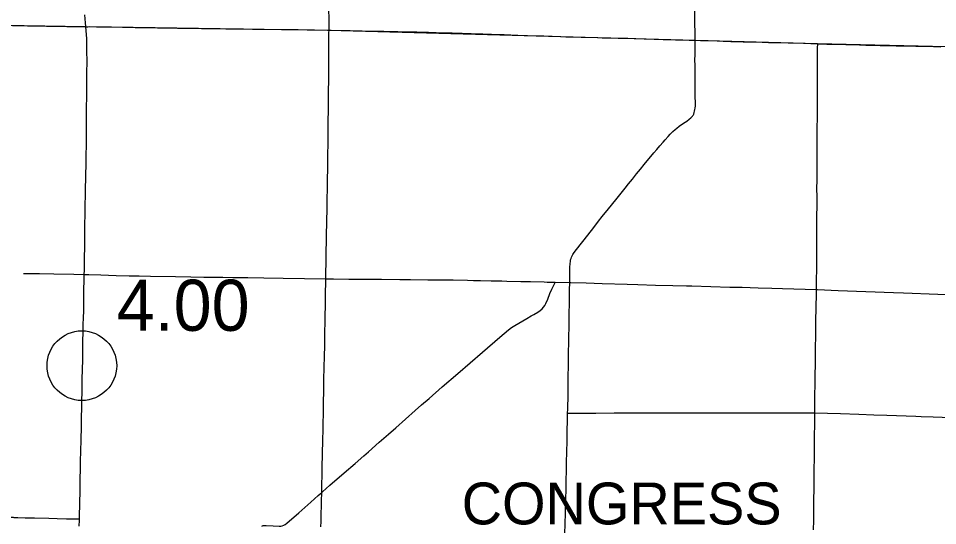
# Model space of a CAD drawing. Extents: x 1813937 to 1948437, y 826606 to 1022856.
# Drawn here: x 1893278 to 1913070, y 950713 to 961626 of the extents above; entities that cross this region are included whole.
import ezdxf

# ---------------------------------------------------------------- set-up
doc = ezdxf.new("R2010")
doc.units = 0
for name, color, linetype in [('Default', 7, 'Continuous'), ('GM_X_County_Road', 7, 'Continuous'), ('GM_X_State_Route', 7, 'Continuous'), ('GM_X_Township', 7, 'Continuous'), ('GM_X_Township_Road', 7, 'Continuous'), ('GM_X_Township_Text', 7, 'Continuous')]:
    doc.layers.add(name, color=color, linetype=linetype)

msp = doc.modelspace()

# ---------------------------------------------------------------- linework, layer by layer
at = {"layer": 'Default'}
msp.add_circle((1894644, 954154), 750, dxfattribs=at)
at = {"layer": 'GM_X_County_Road'}
for points in [[(1899966, 961373), (1899966, 961413), (1899967, 961609), (1899965, 961822)], [(1907848, 961156), (1907847, 961339), (1907846, 961503), (1907846, 961831)], [(1893148, 961472), (1893279, 961470), (1893473, 961468), (1893651, 961465), (1893881, 961462), (1894159, 961458), (1894323, 961455), (1894487, 961452), (1894634, 961451), (1894728, 961449)], [(1894728, 961449), (1894957, 961447), (1895120, 961444), (1895516, 961438), (1895795, 961433), (1896057, 961428), (1896271, 961425), (1896497, 961421), (1896706, 961418), (1896911, 961414), (1897223, 961410), (1897502, 961406), (1897748, 961404), (1898125, 961399), (1898322, 961396), (1898568, 961394), (1898945, 961389), (1899076, 961387), (1899305, 961384), (1899517, 961381), (1899651, 961379), (1899930, 961374), (1899966, 961373)], [(1899898, 956020), (1899898, 956033), (1899900, 956197), (1899903, 956329), (1899908, 956575), (1899912, 956870), (1899914, 957017), (1899917, 957181), (1899918, 957246), (1899920, 957312), (1899923, 957476), (1899924, 957558), (1899928, 957787), (1899930, 957919), (1899932, 958001), (1899933, 958083), (1899937, 958230), (1899939, 958328), (1899943, 958590), (1899944, 958689), (1899944, 958770), (1899945, 958853), (1899950, 959017), (1899950, 959115), (1899948, 959197), (1899951, 959443), (1899953, 959623), (1899954, 959755), (1899955, 959919), (1899956, 960033), (1899959, 960329), (1899959, 960443), (1899959, 960575), (1899960, 960689), (1899960, 960788), (1899961, 961017), (1899962, 961165), (1899965, 961313), (1899966, 961373)], [(1899966, 961373), (1900012, 961371), (1900324, 961365), (1900422, 961363), (1900683, 961360), (1900898, 961353), (1901144, 961350), (1901446, 961343), (1901668, 961339), (1901857, 961334), (1902109, 961328), (1902275, 961326), (1902455, 961319), (1902619, 961313), (1902832, 961305), (1903029, 961299), (1903275, 961291), (1903462, 961286), (1903734, 961279), (1904029, 961268), (1904241, 961260), (1904423, 961254), (1904588, 961249), (1904768, 961243), (1904950, 961236), (1905063, 961232), (1905178, 961228), (1905393, 961221), (1905752, 961212), (1905850, 961209), (1906031, 961205), (1906194, 961201), (1906401, 961198), (1906752, 961187), (1906969, 961180), (1907163, 961174), (1907426, 961168), (1907721, 961160), (1907848, 961156)], [(1905149, 955941), (1905149, 955972), (1905151, 956087), (1905154, 956267), (1905158, 956349), (1905163, 956398), (1905169, 956430), (1905177, 956461), (1905187, 956491), (1905201, 956521), (1905216, 956549), (1905244, 956590), (1905294, 956654), (1905540, 956962), (1905670, 957130), (1905770, 957260), (1905851, 957363), (1905985, 957529), (1906140, 957721), (1906346, 957976), (1906418, 958065), (1906499, 958168), (1906589, 958285), (1906671, 958382), (1906754, 958483), (1906813, 958558), (1906896, 958655), (1906960, 958731), (1907025, 958808), (1907091, 958882), (1907161, 958960), (1907203, 959010), (1907267, 959085), (1907311, 959133), (1907369, 959191), (1907417, 959235), (1907454, 959267), (1907507, 959306), (1907601, 959371), (1907668, 959418), (1907721, 959457), (1907759, 959489), (1907783, 959513), (1907793, 959526), (1907803, 959540), (1907811, 959554), (1907818, 959569), (1907830, 959600), (1907839, 959632), (1907846, 959664), (1907851, 959697), (1907854, 959747), (1907854, 959796), (1907853, 959960), (1907853, 960091), (1907852, 960255), (1907850, 960485), (1907848, 960600), (1907846, 960747), (1907847, 960829), (1907848, 960944), (1907848, 961075), (1907848, 961156)], [(1899810, 951427), (1899814, 951568), (1899815, 951633), (1899817, 951764), (1899819, 951879), (1899822, 952027), (1899825, 952191), (1899827, 952305), (1899828, 952371), (1899830, 952436), (1899831, 952502), (1899835, 952600), (1899838, 952731), (1899841, 952911), (1899846, 953124), (1899849, 953269), (1899849, 953348), (1899849, 953396), (1899850, 953460), (1899851, 953509), (1899852, 953607), (1899853, 953722), (1899855, 953837), (1899858, 953935), (1899861, 954033), (1899864, 954180), (1899867, 954295), (1899870, 954377), (1899874, 954557), (1899877, 954688), (1899878, 954770), (1899879, 954918), (1899881, 955049), (1899885, 955262), (1899888, 955410), (1899891, 955640), (1899898, 956020)], [(1899898, 956020), (1899947, 956020), (1900062, 956019), (1900390, 956018), (1900865, 956014), (1901095, 956012), (1901489, 956009), (1901718, 956008), (1902095, 956004), (1902456, 956001), (1902636, 955998), (1902948, 955993), (1903079, 955990), (1903128, 955989), (1903226, 955988), (1903455, 955983), (1903602, 955980), (1903684, 955979), (1903798, 955975), (1904093, 955967), (1904224, 955964), (1904306, 955962), (1904601, 955956), (1904666, 955954), (1904764, 955952), (1904839, 955950)], [(1899810, 951427), (1899824, 951439), (1899984, 951580), (1900294, 951849), (1900531, 952051), (1900717, 952211), (1900816, 952297), (1901049, 952505), (1901246, 952678), (1901405, 952819), (1901823, 953189), (1901958, 953308), (1902119, 953449), (1902403, 953696), (1902740, 953984), (1903273, 954446), (1903643, 954771), (1903832, 954928), (1903897, 954977), (1903966, 955022), (1904222, 955169), (1904322, 955223), (1904378, 955252), (1904462, 955303), (1904516, 955341), (1904552, 955374), (1904584, 955411), (1904612, 955451), (1904635, 955494), (1904675, 955584), (1904723, 955706), (1904761, 955797), (1904804, 955885), (1904827, 955928), (1904839, 955950)], [(1904839, 955950), (1905149, 955941)], [(1905103, 953133), (1905105, 953218), (1905112, 953529), (1905115, 953693), (1905115, 953824), (1905118, 953923), (1905124, 954152), (1905125, 954333), (1905133, 954759), (1905137, 955005), (1905139, 955202), (1905142, 955563), (1905145, 955776), (1905149, 955941)], [(1905149, 955941), (1905174, 955941), (1905502, 955933), (1905846, 955923), (1906387, 955906), (1906616, 955898), (1906993, 955888), (1907370, 955877), (1907665, 955871), (1907780, 955869), (1908190, 955857), (1908599, 955845), (1908862, 955840), (1909206, 955831), (1909501, 955822), (1909730, 955815), (1910463, 955791)], [(1910427, 953140), (1910427, 953232), (1910430, 953446), (1910430, 953544), (1910435, 953725), (1910436, 953872), (1910437, 954003), (1910439, 954135), (1910442, 954332), (1910443, 954512), (1910447, 954824), (1910449, 955021), (1910451, 955152), (1910456, 955366), (1910462, 955743), (1910462, 955759), (1910463, 955791)], [(1910463, 955791), (1910484, 955790), (1910927, 955773), (1912123, 955726), (1912336, 955718), (1913073, 955691), (1913418, 955680), (1913598, 955675), (1913877, 955666), (1914254, 955655), (1914778, 955638), (1915384, 955619), (1915581, 955611), (1915640, 955608), (1915667, 955604), (1915693, 955599)], [(1905046, 950529), (1905052, 950759), (1905057, 950972), (1905060, 951136), (1905067, 951316), (1905069, 951464), (1905073, 951677), (1905078, 951906), (1905083, 952070), (1905094, 952529), (1905097, 952710), (1905101, 953021), (1905101, 953070), (1905103, 953133)], [(1910400, 950624), (1910404, 950820), (1910405, 951001), (1910406, 951132), (1910408, 951296), (1910409, 951477), (1910413, 951674), (1910414, 951887), (1910419, 952199), (1910419, 952396), (1910420, 952478), (1910422, 952609), (1910426, 952921), (1910428, 953117), (1910427, 953140)], [(1898523, 950700), (1898534, 950708), (1898549, 950714), (1898565, 950717), (1898615, 950716), (1898762, 950705), (1898894, 950701), (1898926, 950703), (1898959, 950708), (1898990, 950719), (1899019, 950734), (1899058, 950763), (1899318, 950990), (1899577, 951218), (1899736, 951361), (1899810, 951427)], [(1899792, 950683), (1899794, 950798), (1899796, 950913), (1899797, 950978), (1899801, 951126), (1899806, 951273), (1899809, 951388), (1899810, 951427)]]:
    msp.add_lwpolyline(points, dxfattribs=at)
at = {"layer": 'GM_X_State_Route'}
msp.add_lwpolyline([(1894590, 950698), (1894593, 950829), (1894593, 950855), (1894595, 950961), (1894600, 951141), (1894605, 951519), (1894611, 951732), (1894614, 951912), (1894618, 952142), (1894620, 952273), (1894631, 952601), (1894636, 952798), (1894638, 952929), (1894645, 953356), (1894649, 953635), (1894654, 953831), (1894659, 954110), (1894662, 954242), (1894664, 954389), (1894665, 954504), (1894666, 954635), (1894668, 954734), (1894670, 954824), (1894670, 954865), (1894672, 954980), (1894675, 955045), (1894680, 955176), (1894684, 955340), (1894686, 955439), (1894687, 955537), (1894688, 955636), (1894688, 955668), (1894687, 955701), (1894687, 955783), (1894688, 955815), (1894689, 955864), (1894691, 955913), (1894692, 955978), (1894697, 956110), (1894697, 956114), (1894698, 956208), (1894700, 956323), (1894704, 956519), (1894706, 956667), (1894707, 956880), (1894707, 956946), (1894709, 957061), (1894710, 957143), (1894712, 957241), (1894715, 957356), (1894716, 957438), (1894717, 957536), (1894718, 957602), (1894722, 957831), (1894725, 958028), (1894727, 958127), (1894731, 958291), (1894735, 958454), (1894739, 958684), (1894742, 958897), (1894743, 958996), (1894743, 959012), (1894743, 959028), (1894743, 959061), (1894744, 959094), (1894744, 959127), (1894744, 959176), (1894746, 959258), (1894746, 959307), (1894747, 959422), (1894747, 959504), (1894748, 959684), (1894753, 959963), (1894750, 960160), (1894750, 960324), (1894752, 960455), (1894756, 960701), (1894755, 960931), (1894754, 961095), (1894751, 961194), (1894745, 961276), (1894728, 961449), (1894720, 961531), (1894706, 961705)], dxfattribs=at)
at = {"layer": 'GM_X_Township'}
msp.add_lwpolyline([(1889423, 961536), (1894728, 961453), (1894730, 961440), (1894815, 961451), (1899962, 961375), (1907847, 961159), (1910485, 961083), (1915744, 960965), (1915744, 960672), (1915689, 955598), (1915669, 952972), (1915640, 948490), (1915630, 947868), (1915624, 947610), (1915561, 944982), (1915495, 939674)], dxfattribs=at)
at = {"layer": 'GM_X_Township_Road'}
for points in [[(1907848, 961156), (1907962, 961153), (1908127, 961149), (1908323, 961142), (1908454, 961137), (1908618, 961130), (1908750, 961127), (1908881, 961122), (1909159, 961119), (1909428, 961110), (1909852, 961099), (1910181, 961091), (1910489, 961081)], [(1910463, 955791), (1910464, 955947), (1910466, 956291), (1910467, 956587), (1910472, 956899), (1910473, 957129), (1910472, 957261), (1910471, 957359), (1910474, 957605), (1910474, 957786), (1910472, 957967), (1910474, 958147), (1910478, 958624), (1910478, 958886), (1910480, 959067), (1910480, 959185), (1910480, 959313), (1910481, 959445), (1910482, 959527), (1910483, 959675), (1910485, 959806), (1910485, 960019), (1910486, 960216), (1910485, 960299), (1910484, 960446), (1910485, 960578), (1910486, 960758), (1910486, 960906), (1910485, 961005), (1910488, 961054), (1910489, 961081)], [(1910489, 961081), (1910686, 961075), (1911095, 961063), (1911390, 961055), (1911522, 961051), (1911620, 961050), (1911751, 961048), (1911833, 961046), (1912178, 961037), (1912604, 961030), (1912982, 961019), (1913140, 961016)], [(1893386, 956139), (1893534, 956138)], [(1893534, 956138), (1893731, 956136), (1894044, 956129), (1894472, 956121), (1894697, 956114)], [(1894697, 956114), (1894726, 956114), (1894792, 956113), (1895054, 956106), (1895382, 956094), (1895661, 956087), (1895875, 956084), (1896121, 956083), (1896662, 956074), (1896990, 956067), (1897269, 956061), (1897680, 956057), (1897893, 956054), (1898221, 956048), (1898566, 956042), (1898976, 956038), (1899436, 956028), (1899898, 956020)], [(1905103, 953133), (1905139, 953133), (1905401, 953134), (1905713, 953133), (1906107, 953136), (1906385, 953137), (1906648, 953137), (1906959, 953136), (1907353, 953137), (1907681, 953136), (1907993, 953136), (1908157, 953137), (1908337, 953138), (1908684, 953141)], [(1908684, 953141), (1908698, 953142), (1908944, 953139), (1909436, 953141), (1909912, 953142), (1910420, 953141), (1910427, 953140)], [(1910427, 953140), (1910699, 953130), (1910977, 953122), (1911371, 953109), (1911699, 953099), (1911977, 953091), (1912600, 953066), (1912715, 953060), (1912977, 953051), (1913551, 953030), (1913911, 953017), (1914354, 953002), (1914764, 952989), (1915010, 952982), (1915420, 952971), (1915633, 952967), (1915670, 952967)], [(1893067, 950894), (1893114, 950893), (1893165, 950891), (1893180, 950890), (1893212, 950888), (1893266, 950887), (1893425, 950881), (1893622, 950877), (1893934, 950871), (1894114, 950866), (1894311, 950861), (1894557, 950855), (1894593, 950855)]]:
    msp.add_lwpolyline(points, dxfattribs=at)

# ---------------------------------------------------------------- texts
at = {"layer": 'Default'}
msp.add_text('4.00', height=1100, dxfattribs=at).set_placement((1895394, 954904))
at = {"layer": 'GM_X_Township_Text'}
msp.add_text('CONGRESS', height=900, rotation=0, dxfattribs=at).set_placement((1902823, 950739))

doc.saveas('drawing.dxf')
